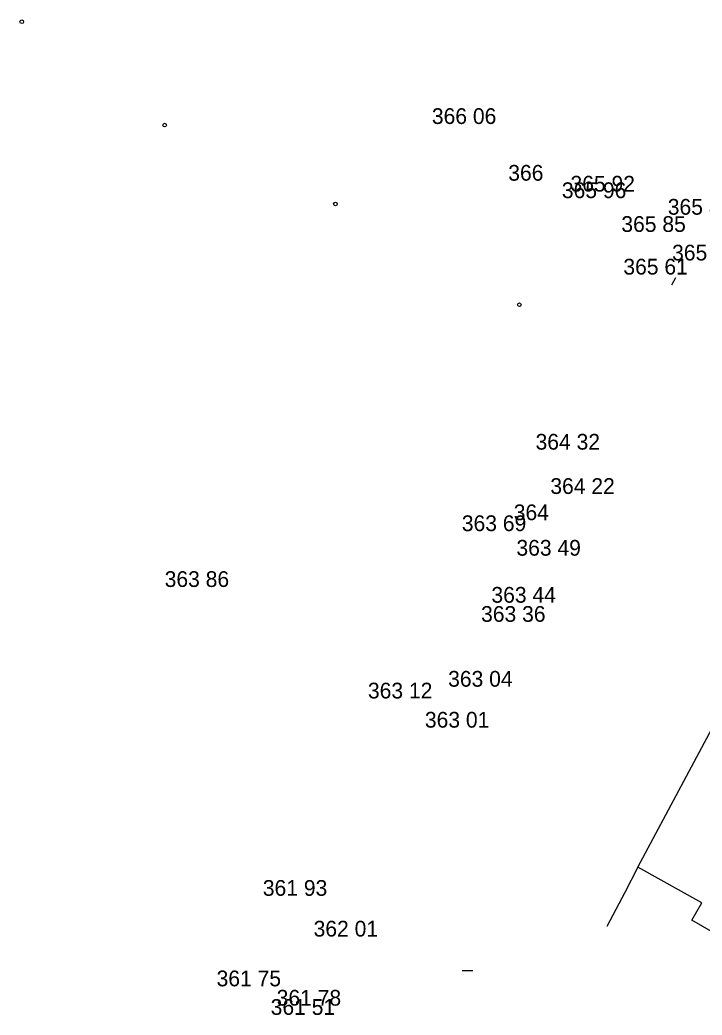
# Model space of a CAD drawing. Extents: x -688316 to -688024, y -973785 to -973591.
# Drawn here: x -688224.06 to -688191.59, y -973699.37 to -973651.97 of the extents above; entities that cross this region are included whole.
import ezdxf

# ---------------------------------------------------------------- set-up
doc = ezdxf.new("R2010")
doc.units = 0
for name, color, linetype in [('Vrstva 3', 7, 'Continuous'), ('Vrstva 5', 7, 'Continuous'), ('Vrstva 58', 7, 'Continuous')]:
    doc.layers.add(name, color=color, linetype=linetype)

# ---------------------------------------------------------------- blocks, each defined once
blk = doc.blocks.new('B_NESP')
at = {"layer": 'Vrstva 58'}
blk.add_circle((0, 0), 0.875, dxfattribs=at)
blk = doc.blocks.new('B_SPAL')
at = {"layer": 'Vrstva 58'}
blk.add_line((-2.5, 0), (2.5, 0), dxfattribs=at)

msp = doc.modelspace()

# ---------------------------------------------------------------- linework, layer by layer
at = {"layer": 'Vrstva 5'}
for p, q in [((-688194.65, -973692.33), (-688181.87, -973668.34)), ((-688194.65, -973692.33), (-688195.27, -973693.53)), ((-688191.6, -973694.02), (-688194.65, -973692.33)), ((-688195.27, -973693.53), (-688196.12, -973695.15)), ((-688192.08, -973694.85), (-688191.6, -973694.02)), ((-688186.17, -973698.25), (-688192.08, -973694.85))]:
    msp.add_line(p, q, dxfattribs=at)
msp.add_lwpolyline([(-688193.027, -973664.595), (-688192.838, -973664.24)], dxfattribs=at)

# ---------------------------------------------------------------- block references
at = {"layer": 'Vrstva 58', "xscale": 0.1, "yscale": 0.10000000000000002}
for name, p in [('B_NESP', (-688223.97, -973652.06)), ('B_NESP', (-688223.97, -973652.06)), ('B_NESP', (-688223.97, -973652.06)), ('B_NESP', (-688223.97, -973652.06)), ('B_NESP', (-688217.17, -973656.98)), ('B_NESP', (-688217.17, -973656.98)), ('B_NESP', (-688217.17, -973656.98)), ('B_NESP', (-688217.17, -973656.98)), ('B_NESP', (-688209.04, -973660.74)), ('B_NESP', (-688209.04, -973660.74)), ('B_NESP', (-688209.04, -973660.74)), ('B_NESP', (-688209.04, -973660.74)), ('B_NESP', (-688200.29, -973665.54)), ('B_NESP', (-688200.29, -973665.54)), ('B_NESP', (-688200.29, -973665.54)), ('B_NESP', (-688200.29, -973665.54)), ('B_SPAL', (-688202.76, -973697.25)), ('B_SPAL', (-688202.76, -973697.25)), ('B_SPAL', (-688202.76, -973697.25)), ('B_SPAL', (-688202.76, -973697.25))]:
    msp.add_blockref(name, p, dxfattribs=at)

# ---------------------------------------------------------------- texts
at = {"layer": 'Vrstva 3'}
for s, p in [('366 06 ', (-688204.453, -973656.93)), ('366 06 ', (-688204.453, -973656.93)), ('366 06 ', (-688204.453, -973656.93)), ('366 06 ', (-688204.453, -973656.93)), ('366 06 ', (-688204.453, -973656.93)), ('366 06 ', (-688204.453, -973656.93)), ('366 06 ', (-688204.453, -973656.93)), ('366    ', (-688200.817, -973659.63)), ('366    ', (-688200.817, -973659.63)), ('366    ', (-688200.817, -973659.63)), ('366    ', (-688200.817, -973659.63)), ('366    ', (-688200.817, -973659.63)), ('366    ', (-688200.817, -973659.63)), ('366    ', (-688200.817, -973659.63)), ('365 96 ', (-688198.266, -973660.46)), ('365 96 ', (-688198.266, -973660.46)), ('365 96 ', (-688198.266, -973660.46)), ('365 96 ', (-688198.266, -973660.46)), ('365 96 ', (-688198.266, -973660.46)), ('365 96 ', (-688198.266, -973660.46)), ('365 96 ', (-688198.266, -973660.46)), ('365 92 ', (-688197.856, -973660.15)), ('365 92 ', (-688197.856, -973660.15)), ('365 92 ', (-688197.856, -973660.15)), ('365 92 ', (-688197.856, -973660.15)), ('365 92 ', (-688197.856, -973660.15)), ('365 92 ', (-688197.856, -973660.15)), ('365 92 ', (-688197.856, -973660.15)), ('365 83 ', (-688193.226, -973661.25)), ('365 83 ', (-688193.226, -973661.25)), ('365 83 ', (-688193.226, -973661.25)), ('365 83 ', (-688193.226, -973661.25)), ('365 83 ', (-688193.226, -973661.25)), ('365 83 ', (-688193.226, -973661.25)), ('365 83 ', (-688193.226, -973661.25)), ('365 85 ', (-688195.436, -973662.07)), ('365 85 ', (-688195.436, -973662.07)), ('365 85 ', (-688195.436, -973662.07)), ('365 85 ', (-688195.436, -973662.07)), ('365 85 ', (-688195.436, -973662.07)), ('365 85 ', (-688195.436, -973662.07)), ('365 85 ', (-688195.436, -973662.07)), ('365 81 ', (-688193.021, -973663.43)), ('365 81 ', (-688193.021, -973663.43)), ('365 81 ', (-688193.021, -973663.43)), ('365 81 ', (-688193.021, -973663.43)), ('365 81 ', (-688193.021, -973663.43)), ('365 81 ', (-688193.021, -973663.43)), ('365 81 ', (-688193.021, -973663.43)), ('365 61 ', (-688195.34, -973664.1)), ('365 61 ', (-688195.34, -973664.1)), ('365 61 ', (-688195.34, -973664.1)), ('365 61 ', (-688195.34, -973664.1)), ('365 61 ', (-688195.34, -973664.1)), ('365 61 ', (-688195.34, -973664.1)), ('365 61 ', (-688195.34, -973664.1)), ('364 32 ', (-688199.518, -973672.44)), ('364 32 ', (-688199.518, -973672.44)), ('364 32 ', (-688199.518, -973672.44)), ('364 32 ', (-688199.518, -973672.44)), ('364 32 ', (-688199.518, -973672.44)), ('364 32 ', (-688199.518, -973672.44)), ('364 32 ', (-688199.518, -973672.44)), ('364 22 ', (-688198.816, -973674.55)), ('364 22 ', (-688198.816, -973674.55)), ('364 22 ', (-688198.816, -973674.55)), ('364 22 ', (-688198.816, -973674.55)), ('364 22 ', (-688198.816, -973674.55)), ('364 22 ', (-688198.816, -973674.55)), ('364 22 ', (-688198.816, -973674.55)), ('364    ', (-688200.557, -973675.8)), ('364    ', (-688200.557, -973675.8)), ('364    ', (-688200.557, -973675.8)), ('364    ', (-688200.557, -973675.8)), ('364    ', (-688200.557, -973675.8)), ('364    ', (-688200.557, -973675.8)), ('364    ', (-688200.557, -973675.8)), ('363 69 ', (-688203.028, -973676.32)), ('363 69 ', (-688203.028, -973676.32)), ('363 69 ', (-688203.028, -973676.32)), ('363 69 ', (-688203.028, -973676.32)), ('363 69 ', (-688203.028, -973676.32)), ('363 69 ', (-688203.028, -973676.32)), ('363 69 ', (-688203.028, -973676.32)), ('363 49 ', (-688200.429, -973677.49)), ('363 49 ', (-688200.429, -973677.49)), ('363 49 ', (-688200.429, -973677.49)), ('363 49 ', (-688200.429, -973677.49)), ('363 49 ', (-688200.429, -973677.49)), ('363 49 ', (-688200.429, -973677.49)), ('363 49 ', (-688200.429, -973677.49)), ('363 86 ', (-688217.169, -973678.98)), ('363 86 ', (-688217.169, -973678.98)), ('363 86 ', (-688217.169, -973678.98)), ('363 86 ', (-688217.169, -973678.98)), ('363 86 ', (-688217.169, -973678.98)), ('363 86 ', (-688217.169, -973678.98)), ('363 86 ', (-688217.169, -973678.98)), ('363 44 ', (-688201.619, -973679.73)), ('363 44 ', (-688201.619, -973679.73)), ('363 44 ', (-688201.619, -973679.73)), ('363 44 ', (-688201.619, -973679.73)), ('363 44 ', (-688201.619, -973679.73)), ('363 44 ', (-688201.619, -973679.73)), ('363 44 ', (-688201.619, -973679.73)), ('363 36 ', (-688202.111, -973680.64)), ('363 36 ', (-688202.111, -973680.64)), ('363 36 ', (-688202.111, -973680.64)), ('363 36 ', (-688202.111, -973680.64)), ('363 36 ', (-688202.111, -973680.64)), ('363 36 ', (-688202.111, -973680.64)), ('363 36 ', (-688202.111, -973680.64)), ('363 04 ', (-688203.679, -973683.73)), ('363 04 ', (-688203.679, -973683.73)), ('363 04 ', (-688203.679, -973683.73)), ('363 04 ', (-688203.679, -973683.73)), ('363 04 ', (-688203.679, -973683.73)), ('363 04 ', (-688203.679, -973683.73)), ('363 04 ', (-688203.679, -973683.73)), ('363 12 ', (-688207.495, -973684.29)), ('363 12 ', (-688207.495, -973684.29)), ('363 12 ', (-688207.495, -973684.29)), ('363 12 ', (-688207.495, -973684.29)), ('363 12 ', (-688207.495, -973684.29)), ('363 12 ', (-688207.495, -973684.29)), ('363 12 ', (-688207.495, -973684.29)), ('363 01 ', (-688204.785, -973685.68)), ('363 01 ', (-688204.785, -973685.68)), ('363 01 ', (-688204.785, -973685.68)), ('363 01 ', (-688204.785, -973685.68)), ('363 01 ', (-688204.785, -973685.68)), ('363 01 ', (-688204.785, -973685.68)), ('363 01 ', (-688204.785, -973685.68)), ('361 93 ', (-688212.498, -973693.69)), ('361 93 ', (-688212.498, -973693.69)), ('361 93 ', (-688212.498, -973693.69)), ('361 93 ', (-688212.498, -973693.69)), ('361 93 ', (-688212.498, -973693.69)), ('361 93 ', (-688212.498, -973693.69)), ('361 93 ', (-688212.498, -973693.69)), ('362 01 ', (-688210.081, -973695.63)), ('362 01 ', (-688210.081, -973695.63)), ('362 01 ', (-688210.081, -973695.63)), ('362 01 ', (-688210.081, -973695.63)), ('362 01 ', (-688210.081, -973695.63)), ('362 01 ', (-688210.081, -973695.63)), ('362 01 ', (-688210.081, -973695.63)), ('361 75 ', (-688214.698, -973698)), ('361 75 ', (-688214.698, -973698)), ('361 75 ', (-688214.698, -973698)), ('361 75 ', (-688214.698, -973698)), ('361 75 ', (-688214.698, -973698)), ('361 75 ', (-688214.698, -973698)), ('361 75 ', (-688214.698, -973698)), ('361 78 ', (-688211.838, -973698.92)), ('361 78 ', (-688211.838, -973698.92)), ('361 78 ', (-688211.838, -973698.92)), ('361 78 ', (-688211.838, -973698.92)), ('361 78 ', (-688211.838, -973698.92)), ('361 78 ', (-688211.838, -973698.92)), ('361 78 ', (-688211.838, -973698.92)), ('361 51 ', (-688212.124, -973699.36)), ('361 51 ', (-688212.124, -973699.36)), ('361 51 ', (-688212.124, -973699.36)), ('361 51 ', (-688212.124, -973699.36)), ('361 51 ', (-688212.124, -973699.36)), ('361 51 ', (-688212.124, -973699.36)), ('361 51 ', (-688212.124, -973699.36))]:
    msp.add_text(s, height=0.75, dxfattribs=at).set_placement(p)

doc.saveas('drawing.dxf')
